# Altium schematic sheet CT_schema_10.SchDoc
size 147 x 119 mm
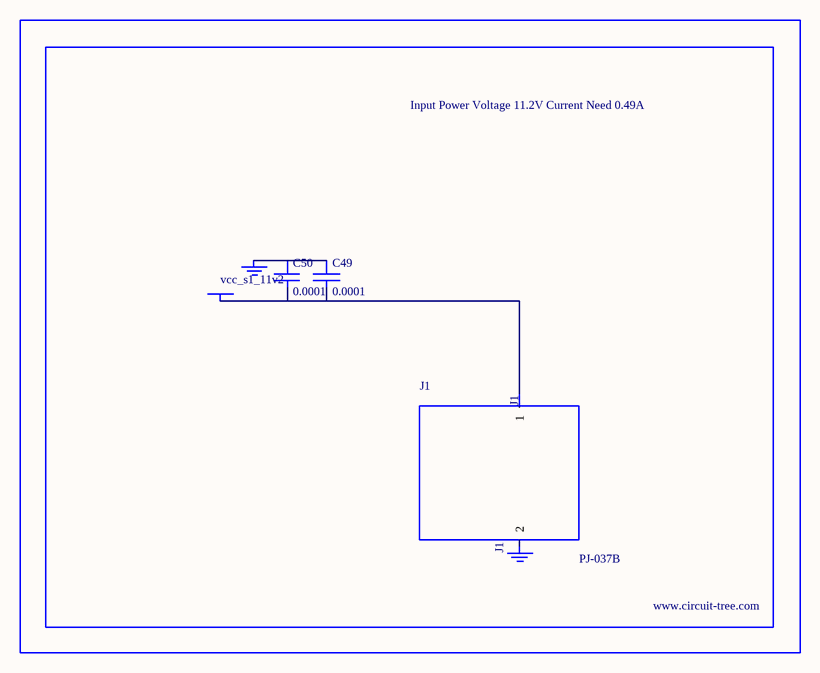
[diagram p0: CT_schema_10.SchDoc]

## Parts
BORDER9  (no value)
C49  0.0001  [EXV-9H]
C50  0.0001  [EXV-9H]
GND_INSTANCE_9_0  (no value)
GND_INSTANCE_9_1  (no value)
J1  PJ-037B  [PJ-037B_PACKAGE]
POWER_INSTANCE_9_0  vcc_s1_11v2

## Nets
NetC49_1: C49.1 C50.1 GND_INSTANCE_9_0.0(GND)
NetC49_2: C49.2 C50.2 J1.1 POWER_INSTANCE_9_0.0(PWR)

Not connected (* = marked no-connect by the designer): GND_INSTANCE_9_1 0(GND); J1 2

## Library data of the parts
BORDER9 = BORDER_PAGE9
C49 C50 = EDK107M035A9HAA
GND_INSTANCE_9_0 GND_INSTANCE_9_1 = GND
POWER_INSTANCE_9_0 = PWR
